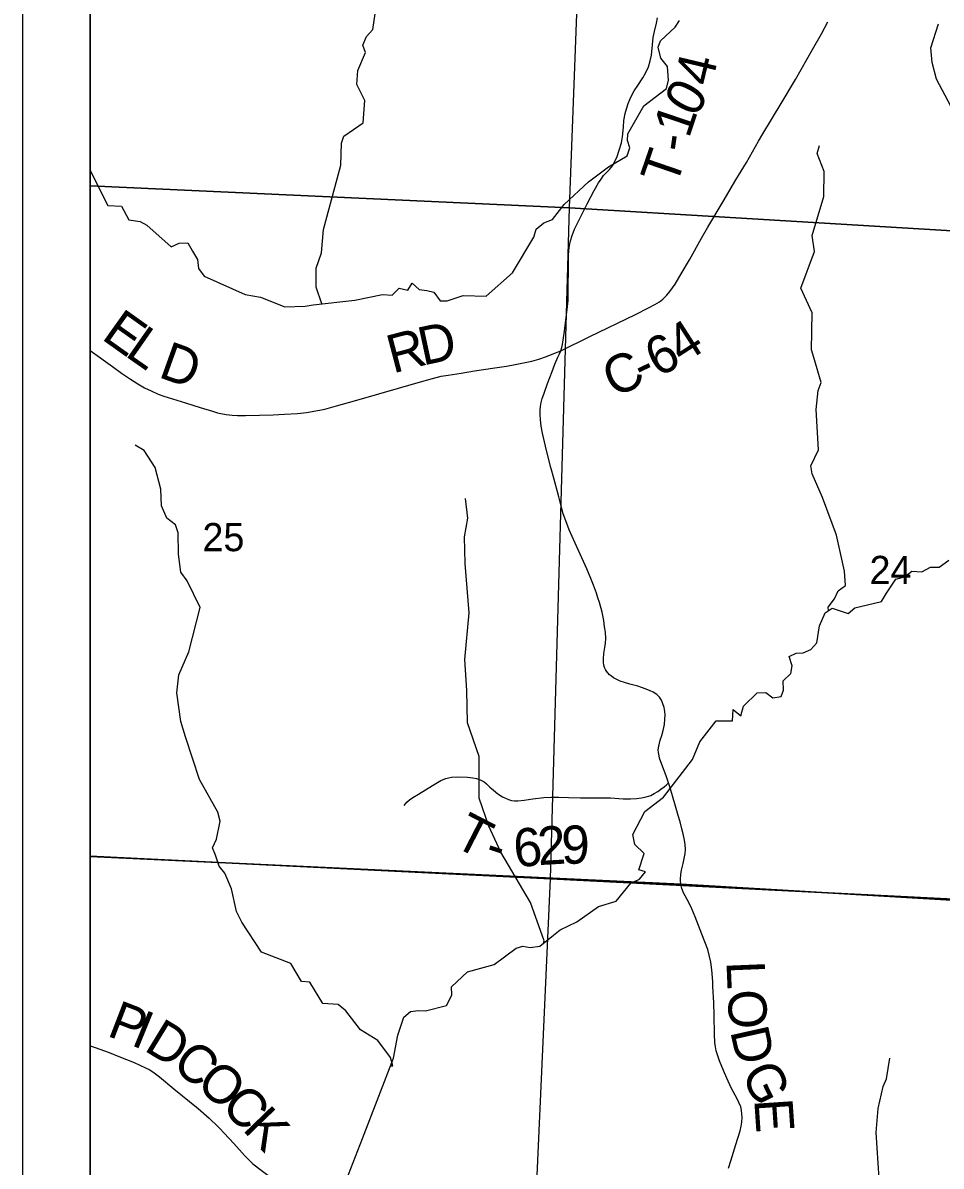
# Model space of a CAD drawing. Extents: x 0 to 34, y 0 to 22.
# Drawn here: x 23.917 to 25.281, y 17.98 to 19.68 of the extents above; entities that cross this region are included whole.
import ezdxf

# ---------------------------------------------------------------- set-up
doc = ezdxf.new("R2010")
doc.units = 0
for name, color, linetype in [('GM_X_Adjacent_County', 7, 'Continuous'), ('GM_X_County', 7, 'Continuous'), ('GM_X_County_Road', 7, 'Continuous'), ('GM_X_County_Road_Text', 7, 'Continuous'), ('GM_X_Minor_River', 7, 'Continuous'), ('GM_X_Section', 7, 'Continuous'), ('GM_X_Section_Text', 7, 'Continuous'), ('GM_X_Township', 7, 'Continuous'), ('GM_X_Township_Road', 7, 'Continuous'), ('GM_X_Township_Road_Text', 7, 'Continuous'), ('SH_Data', 7, 'Continuous')]:
    doc.layers.add(name, color=color, linetype=linetype)

msp = doc.modelspace()

# ---------------------------------------------------------------- linework, layer by layer
at = {"layer": 'GM_X_Adjacent_County'}
msp.add_lwpolyline([(28.7526, 20.9), (24.0167, 20.9), (24.0167, 14.1), (28.5181, 14.1)], dxfattribs=at)
at = {"layer": 'GM_X_County'}
msp.add_lwpolyline([(28.7526, 20.9), (24.0167, 20.9), (24.0167, 14.1), (28.5181, 14.1)], dxfattribs=at)
at = {"layer": 'GM_X_County_Road'}
for points in [[(24.7158, 19.1923), (24.7589, 19.2133), (24.8269, 19.2462), (24.846, 19.2562), (24.8555, 19.2608), (24.8625, 19.2651), (24.8676, 19.2689), (24.8735, 19.2748), (24.8779, 19.2805), (24.8857, 19.2912), (24.8948, 19.3066), (24.907, 19.3274), (24.9248, 19.3595), (24.9345, 19.3759), (24.9574, 19.4142), (24.976, 19.4463), (24.9917, 19.4722), (25.0099, 19.5039), (25.0162, 19.5147), (25.0432, 19.5596), (25.0648, 19.5955), (25.0901, 19.6402), (25.1033, 19.6631), (25.1127, 19.6813)], [(24.0167, 19.1925), (24.02, 19.1901), (24.0496, 19.1688), (24.0634, 19.1588), (24.0766, 19.1497), (24.0877, 19.1429), (24.0976, 19.137), (24.1073, 19.1324), (24.1176, 19.1278), (24.1262, 19.1246), (24.1389, 19.1205), (24.1583, 19.1146), (24.1799, 19.1078), (24.1982, 19.1025), (24.2058, 19.1), (24.2106, 19.099), (24.2187, 19.0973), (24.2276, 19.0963), (24.2357, 19.096), (24.2473, 19.096), (24.2684, 19.0965), (24.2888, 19.0971), (24.3056, 19.0979), (24.3245, 19.099), (24.3379, 19.1006), (24.352, 19.1027), (24.3652, 19.1054), (24.3827, 19.1105), (24.4094, 19.1178), (24.4458, 19.1281), (24.5041, 19.1451), (24.5254, 19.151), (24.538, 19.1542), (24.5486, 19.1561), (24.568, 19.1591), (24.5879, 19.1623), (24.6181, 19.1669), (24.6351, 19.1693), (24.6483, 19.1715), (24.6629, 19.1745), (24.6729, 19.1769), (24.6831, 19.1799), (24.6945, 19.1836), (24.7055, 19.1879), (24.7158, 19.1923)], [(24.876, 18.5496), (24.8723, 18.5603), (24.866, 18.577), (24.8628, 18.5866), (24.862, 18.5901), (24.8612, 18.5948), (24.8608, 18.5987), (24.8615, 18.6043), (24.8637, 18.6132), (24.8661, 18.6204), (24.8682, 18.6275), (24.8699, 18.6366), (24.8707, 18.6444), (24.8709, 18.6507), (24.8707, 18.6558), (24.8693, 18.662), (24.8677, 18.6674), (24.8655, 18.6727), (24.8628, 18.6771), (24.8585, 18.6811), (24.8531, 18.6846), (24.8486, 18.6868), (24.8426, 18.6892), (24.8358, 18.6916), (24.8302, 18.6933), (24.8186, 18.6966), (24.8108, 18.6989), (24.8041, 18.7011), (24.7983, 18.7039), (24.7944, 18.706), (24.7912, 18.7084), (24.7885, 18.7106), (24.7838, 18.7156), (24.7823, 18.7182), (24.781, 18.7215), (24.7801, 18.725), (24.7795, 18.7289), (24.7792, 18.7343), (24.7801, 18.7423), (24.7815, 18.751), (24.7822, 18.7577), (24.7827, 18.7645), (24.7822, 18.7736), (24.781, 18.7817), (24.7798, 18.7912), (24.7774, 18.8033), (24.7733, 18.8179), (24.7712, 18.8249), (24.769, 18.8316), (24.7644, 18.8437), (24.7604, 18.8535), (24.7544, 18.8678), (24.7474, 18.8842), (24.7372, 18.9063), (24.7285, 18.926), (24.7234, 18.9395), (24.7196, 18.9495), (24.7159, 18.963), (24.7132, 18.9751), (24.7056, 19.0026), (24.701, 19.0188), (24.6948, 19.0439), (24.6889, 19.0695), (24.687, 19.08), (24.6859, 19.0894), (24.6854, 19.0975), (24.6854, 19.104), (24.6859, 19.1094), (24.6867, 19.1151), (24.6884, 19.121), (24.6905, 19.1275), (24.6962, 19.1436), (24.7029, 19.1612), (24.707, 19.172), (24.7116, 19.1825), (24.7139, 19.1877), (24.7158, 19.1923)], [(24.894, 18.4042), (24.8939, 18.4068), (24.8941, 18.4137), (24.8955, 18.4201), (24.8979, 18.43), (24.8993, 18.4373), (24.9007, 18.4449), (24.901, 18.4507), (24.9006, 18.458), (24.8998, 18.4646), (24.8978, 18.4741), (24.8959, 18.4813), (24.8931, 18.492), (24.8904, 18.5015), (24.8863, 18.5149), (24.8786, 18.5424), (24.876, 18.5496)], [(24.9652, 17.977), (24.9684, 17.988), (24.976, 18.012), (24.9822, 18.0325), (24.9841, 18.0393), (24.9849, 18.0455), (24.9852, 18.0525), (24.9849, 18.0573), (24.9843, 18.063), (24.9833, 18.0681), (24.9807, 18.0746), (24.9782, 18.0802), (24.9693, 18.0966), (24.9625, 18.1106), (24.9576, 18.1221), (24.9519, 18.1365), (24.9488, 18.1453), (24.947, 18.1513), (24.9456, 18.1574), (24.9448, 18.1637), (24.9444, 18.1761), (24.9439, 18.204), (24.9431, 18.2226), (24.942, 18.2475), (24.9417, 18.2545), (24.9404, 18.272), (24.939, 18.2831), (24.9371, 18.2917), (24.9343, 18.302), (24.93, 18.3134), (24.9254, 18.3247), (24.9156, 18.3504), (24.9104, 18.3626), (24.9061, 18.3718), (24.8982, 18.3861), (24.8959, 18.3926), (24.8943, 18.3993), (24.894, 18.4042)]]:
    msp.add_lwpolyline(points, dxfattribs=at)
at = {"layer": 'GM_X_Minor_River'}
for points in [[(24.361, 19.2618), (24.3522, 19.2868), (24.3524, 19.3149), (24.3603, 19.3377), (24.3631, 19.3722), (24.3835, 19.4478), (24.3891, 19.468), (24.39, 19.501), (24.3938, 19.5112), (24.4221, 19.5308), (24.4249, 19.5642), (24.413, 19.588), (24.4144, 19.6088), (24.4257, 19.6355), (24.4218, 19.6464), (24.4274, 19.6594), (24.4368, 19.67), (24.4474, 19.7437), (24.4537, 19.7718), (24.4649, 19.8007)], [(24.0167, 19.4601), (24.0427, 19.4079), (24.0632, 19.4072), (24.0739, 19.3868), (24.091, 19.3843), (24.1009, 19.379), (24.137, 19.3466), (24.1488, 19.352), (24.1616, 19.3525), (24.1685, 19.34), (24.1762, 19.3279), (24.1774, 19.3146), (24.1862, 19.3029), (24.2469, 19.276), (24.2697, 19.2716), (24.3061, 19.2574), (24.3361, 19.2583), (24.3482, 19.2603), (24.4099, 19.2675), (24.4508, 19.2757), (24.4652, 19.2746), (24.4757, 19.2853), (24.4886, 19.2823), (24.495, 19.2926), (24.5053, 19.2832), (24.5167, 19.2817), (24.5273, 19.2795), (24.5368, 19.2663), (24.5471, 19.2664), (24.5709, 19.2745), (24.605, 19.2735), (24.6442, 19.3079), (24.6761, 19.3608), (24.6791, 19.373), (24.6908, 19.3825), (24.7036, 19.3875), (24.7209, 19.4096), (24.7571, 19.4432), (24.7866, 19.4658), (24.8145, 19.4819), (24.8186, 19.494), (24.8148, 19.5046), (24.8155, 19.5145), (24.8391, 19.5563), (24.8731, 19.582), (24.876, 19.5945), (24.8744, 19.615), (24.8645, 19.6274), (24.8606, 19.6433), (24.864, 19.6528), (24.8858, 19.6731), (24.8922, 19.6833)], [(25.2999, 19.5473), (25.2743, 19.5957), (25.2677, 19.6207), (25.2657, 19.6426), (25.2772, 19.678)], [(25.1138, 18.806), (25.1131, 18.8111), (25.1228, 18.8233), (25.1281, 18.8355), (25.139, 18.8431), (25.1374, 18.8644), (25.1257, 18.9182), (25.1049, 18.9738), (25.0892, 19.0093), (25.0873, 19.0211), (25.0989, 19.0451), (25.0955, 19.105), (25.0984, 19.133), (25.1029, 19.1452), (25.092, 19.1823), (25.0886, 19.1937), (25.0894, 19.2487), (25.0725, 19.285), (25.0927, 19.3397), (25.0895, 19.3636), (25.1066, 19.4217), (25.1072, 19.4589), (25.0968, 19.4854), (25.1005, 19.4972)], [(24.463, 18.1292), (24.4663, 18.1292), (24.4628, 18.1417), (24.4441, 18.1666), (24.4182, 18.1824), (24.3965, 18.2107), (24.3851, 18.2201), (24.3623, 18.2219), (24.3432, 18.2536), (24.3307, 18.2547), (24.3146, 18.2811), (24.271, 18.2979), (24.2419, 18.3425), (24.2342, 18.3584), (24.2265, 18.3921), (24.2165, 18.4156), (24.2081, 18.4261), (24.2027, 18.4424), (24.1985, 18.4534), (24.2045, 18.4659), (24.2096, 18.4929), (24.2065, 18.5061), (24.1793, 18.5549), (24.1582, 18.6181), (24.1512, 18.6408), (24.1453, 18.6837), (24.1482, 18.7106), (24.1631, 18.7445), (24.1802, 18.8106), (24.161, 18.8503), (24.1515, 18.8631), (24.1479, 18.8896), (24.1474, 18.9215), (24.1435, 18.9332), (24.1306, 18.9434), (24.1225, 18.9616), (24.1216, 18.9862), (24.1131, 19.0184), (24.0967, 19.0441), (24.0834, 19.052)], [(24.69, 18.3115), (24.6914, 18.3148), (24.671, 18.372), (24.6267, 18.4468), (24.609, 18.4854), (24.5944, 18.527), (24.5944, 18.5889), (24.5775, 18.6388), (24.5764, 18.687), (24.5732, 18.7333), (24.58, 18.8027), (24.5739, 18.8759), (24.5729, 18.9153), (24.5777, 18.9434), (24.5741, 18.9726)], [(24.3971, 17.9585), (24.4214, 18.0212), (24.4673, 18.1406), (24.4736, 18.1747), (24.4829, 18.2013), (24.4927, 18.2097), (24.5045, 18.2113), (24.5151, 18.211), (24.5461, 18.2188), (24.554, 18.2344), (24.5535, 18.2465), (24.5773, 18.269), (24.617, 18.2799), (24.6498, 18.304), (24.6597, 18.3071), (24.6703, 18.3052), (24.6847, 18.3072), (24.705, 18.3236), (24.7152, 18.3313), (24.7398, 18.3432), (24.7719, 18.3658), (24.7983, 18.3739), (24.8198, 18.4009), (24.833, 18.4067), (24.842, 18.4177), (24.8318, 18.4207), (24.8396, 18.4447), (24.8259, 18.4579), (24.8228, 18.473), (24.8408, 18.5072), (24.8687, 18.5283), (24.9116, 18.5843), (24.9224, 18.6109), (24.9469, 18.6418), (24.9711, 18.6419), (24.9718, 18.659), (24.9832, 18.6496), (24.9873, 18.664), (25.0077, 18.6838), (25.0205, 18.6839), (25.0312, 18.6764), (25.0433, 18.678), (25.0467, 18.6875), (25.0462, 18.7015), (25.0575, 18.7122), (25.0597, 18.7236), (25.0551, 18.7376), (25.0657, 18.7426), (25.0759, 18.743), (25.0876, 18.748), (25.0963, 18.7579), (25.1003, 18.7834), (25.1089, 18.8028), (25.1191, 18.8096), (25.143, 18.8014), (25.1528, 18.8098), (25.1922, 18.8195), (25.1997, 18.8317), (25.2136, 18.8527), (25.2265, 18.8562), (25.2374, 18.8646), (25.2522, 18.8635), (25.2654, 18.8704), (25.2783, 18.8705), (25.2923, 18.8808)], [(25.1866, 17.8493), (25.189, 17.9616), (25.1845, 18.0298), (25.1877, 18.0659), (25.1947, 18.0985), (25.1999, 18.1096), (25.2047, 18.1407)]]:
    msp.add_lwpolyline(points, dxfattribs=at)
at = {"layer": 'GM_X_Section'}
for p, q in [((24.0167, 20.4434), (24.0167, 19.4375)), ((24.0167, 19.4375), (24.0167, 18.4409)), ((24.0167, 18.4409), (24.0167, 17.3235))]:
    msp.add_line(p, q, dxfattribs=at)
for points in [[(24.0167, 19.4375), (24.7287, 19.4048), (24.7666, 20.401), (24.0167, 20.4434)], [(24.0167, 18.4409), (24.7007, 18.4069), (24.7287, 19.4048), (24.0167, 19.4375)], [(24.0167, 17.3235), (24.6507, 17.2941), (24.7007, 18.4069), (24.0167, 18.4409)]]:
    msp.add_lwpolyline(points, dxfattribs=at)
for points in [[(24.7666, 20.401), (25.7533, 20.3558), (25.7174, 19.3453), (24.7287, 19.4048)], [(24.7287, 19.4048), (25.7174, 19.3453), (25.6829, 18.3575), (24.7007, 18.4069)], [(24.7007, 18.4069), (25.6829, 18.3575), (25.6316, 17.2576), (24.6507, 17.2941)]]:
    msp.add_lwpolyline(points, close=True, dxfattribs=at)
at = {"layer": 'GM_X_Township'}
for points in [[(28.7526, 20.9), (24.0167, 20.9), (24.0167, 18.4402)], [(24.0167, 18.4402), (24.8943, 18.3993), (25.406, 18.3689), (26.4836, 18.3303), (26.4899, 18.3297), (26.5001, 18.3293), (26.5159, 18.3284), (26.5253, 18.328), (26.5375, 18.3271), (26.5551, 18.3258), (26.5706, 18.3249), (26.5923, 18.324), (26.6434, 18.3221), (26.6499, 18.322)], [(26.6499, 18.322), (26.6434, 18.3221), (26.5923, 18.324), (26.5706, 18.3249), (26.5551, 18.3258), (26.5375, 18.3271), (26.5253, 18.328), (26.5159, 18.3284), (26.5001, 18.3293), (26.4899, 18.3297), (26.4836, 18.3303), (25.406, 18.3689), (24.8943, 18.3993), (24.0167, 18.4402)], [(24.0167, 18.4402), (24.0167, 14.1), (28.5181, 14.1)]]:
    msp.add_lwpolyline(points, dxfattribs=at)
at = {"layer": 'GM_X_Township_Road'}
for points in [[(24.7158, 19.1923), (24.7175, 19.1972), (24.7184, 19.2016), (24.72, 19.2112), (24.7213, 19.2212), (24.7235, 19.2377), (24.7256, 19.2533), (24.7267, 19.2671), (24.727, 19.2876), (24.7272, 19.314), (24.7272, 19.3331), (24.7278, 19.3418), (24.7289, 19.3488), (24.7302, 19.3555), (24.7326, 19.3633), (24.7361, 19.3731), (24.7394, 19.379), (24.7461, 19.3927), (24.7553, 19.4105), (24.7655, 19.4302), (24.772, 19.4416), (24.7758, 19.4475), (24.7795, 19.4525), (24.784, 19.4574), (24.7885, 19.4615), (24.7929, 19.467), (24.7964, 19.4735), (24.7996, 19.4811), (24.8028, 19.4903), (24.8059, 19.5012), (24.8077, 19.5104), (24.8093, 19.5245), (24.8098, 19.5343), (24.8114, 19.5448), (24.8138, 19.5532), (24.816, 19.56), (24.8184, 19.5656), (24.8214, 19.5721), (24.8249, 19.5786), (24.8305, 19.5864), (24.8378, 19.5978), (24.8422, 19.6059), (24.846, 19.6145), (24.8489, 19.6233), (24.8505, 19.6314), (24.8524, 19.6468), (24.8534, 19.6578), (24.8552, 19.6667), (24.8583, 19.6794), (24.8594, 19.6872)], [(24.4832, 18.5161), (24.485, 18.5186), (24.487, 18.521), (24.4913, 18.5247), (24.4962, 18.5281), (24.5045, 18.5329), (24.5253, 18.5458), (24.5329, 18.5505), (24.5379, 18.5531), (24.5413, 18.555), (24.5452, 18.5565), (24.549, 18.5575), (24.5535, 18.5582), (24.5629, 18.5586), (24.5774, 18.5583), (24.5852, 18.5573), (24.5907, 18.5561), (24.5962, 18.5541), (24.6019, 18.5513), (24.6056, 18.5485), (24.6107, 18.5435), (24.6158, 18.5391), (24.6226, 18.5334), (24.6294, 18.5292), (24.6339, 18.5268), (24.6384, 18.5248), (24.6427, 18.5236), (24.647, 18.5232), (24.6519, 18.5232), (24.6614, 18.5241), (24.6746, 18.526), (24.6908, 18.5279), (24.7018, 18.5284), (24.7132, 18.5284), (24.7272, 18.5281), (24.7453, 18.5273), (24.7706, 18.5273), (24.79, 18.5273), (24.8085, 18.5259), (24.8196, 18.5258), (24.8285, 18.5263), (24.8357, 18.5273), (24.8426, 18.529), (24.8499, 18.5311), (24.8548, 18.5338), (24.8599, 18.537), (24.8647, 18.5403), (24.8693, 18.5437), (24.873, 18.547), (24.876, 18.5496)], [(24.0167, 18.1589), (24.0243, 18.1562), (24.0447, 18.1487), (24.0592, 18.1432), (24.0822, 18.134), (24.099, 18.1262), (24.1044, 18.1235), (24.1098, 18.1202), (24.1198, 18.1129), (24.1412, 18.0951), (24.177, 18.0655), (24.1935, 18.0514), (24.2068, 18.0384), (24.2091, 18.036), (24.2158, 18.0289), (24.2302, 18.0135), (24.2464, 17.9954), (24.2584, 17.9836), (24.2705, 17.9739), (24.2906, 17.9592), (24.3022, 17.9513)]]:
    msp.add_lwpolyline(points, dxfattribs=at)
at = {"layer": 'SH_Data'}
for points in [[(23.9167, 21), (30.9167, 21), (30.9167, 14), (23.9167, 14)], [(24.0167, 20.9), (30.8167, 20.9), (30.8167, 14.1), (24.0167, 14.1)]]:
    msp.add_lwpolyline(points, close=True, dxfattribs=at)

# ---------------------------------------------------------------- texts
at = {"layer": 'GM_X_County_Road_Text'}
for s, rotation, p in [('E', 324.5552, (24.0318, 19.2105)), ('L', 325.0474, (24.0668, 19.1855)), ('R', 14.7273, (24.4664, 19.1582)), ('D', 12.1258, (24.5109, 19.17)), ('4', 32.6996, (24.8967, 19.1712)), ('6', 26.7591, (24.8599, 19.1522)), ('D', 340.2858, (24.1163, 19.1536)), ('C', 25.2925, (24.7952, 19.1216)), ('-', 25.5104, (24.8376, 19.1416)), ('L', 272.4049, (24.962, 18.2841)), ('O', 272.4163, (24.9638, 18.2416)), ('D', 282.5611, (24.9674, 18.1808)), ('G', 295.8679, (24.983, 18.1184)), ('E', 273.8429, (25.0033, 18.0789))]:
    msp.add_text(s, height=0.0568, rotation=rotation, dxfattribs=at).set_placement(p)
at = {"layer": 'GM_X_Section_Text'}
for s, p in [('25', (24.1835, 18.8942)), ('24', (25.1747, 18.8454))]:
    msp.add_text(s, height=0.04186, rotation=0, dxfattribs=at).set_placement(p)
at = {"layer": 'GM_X_Township_Road_Text'}
for s, rotation, p in [('4', 76.5902, (24.9397, 19.5838)), ('0', 60.5643, (24.9162, 19.5373)), ('1', 71.4202, (24.9062, 19.5067)), ('T', 71.0067, (24.887, 19.4345)), ('-', 82.0322, (24.9036, 19.4863)), ('T', 332.7718, (24.5538, 18.4571)), ('6', 6.0419, (24.6486, 18.4237)), ('2', 3.3741, (24.6827, 18.4274)), ('9', 0.5152, (24.7169, 18.4294)), ('-', 341.4737, (24.6003, 18.434)), ('P', 338.9212, (24.04, 18.1743)), ('I', 337.726, (24.0754, 18.1606)), ('D', 328.6364, (24.0949, 18.1529)), ('C', 320.7166, (24.1359, 18.128)), ('O', 320.2131, (24.1719, 18.0986)), ('C', 314.0036, (24.2091, 18.0677)), ('K', 314.0937, (24.2416, 18.0341))]:
    msp.add_text(s, height=0.0568, rotation=rotation, dxfattribs=at).set_placement(p)

doc.saveas('drawing.dxf')
